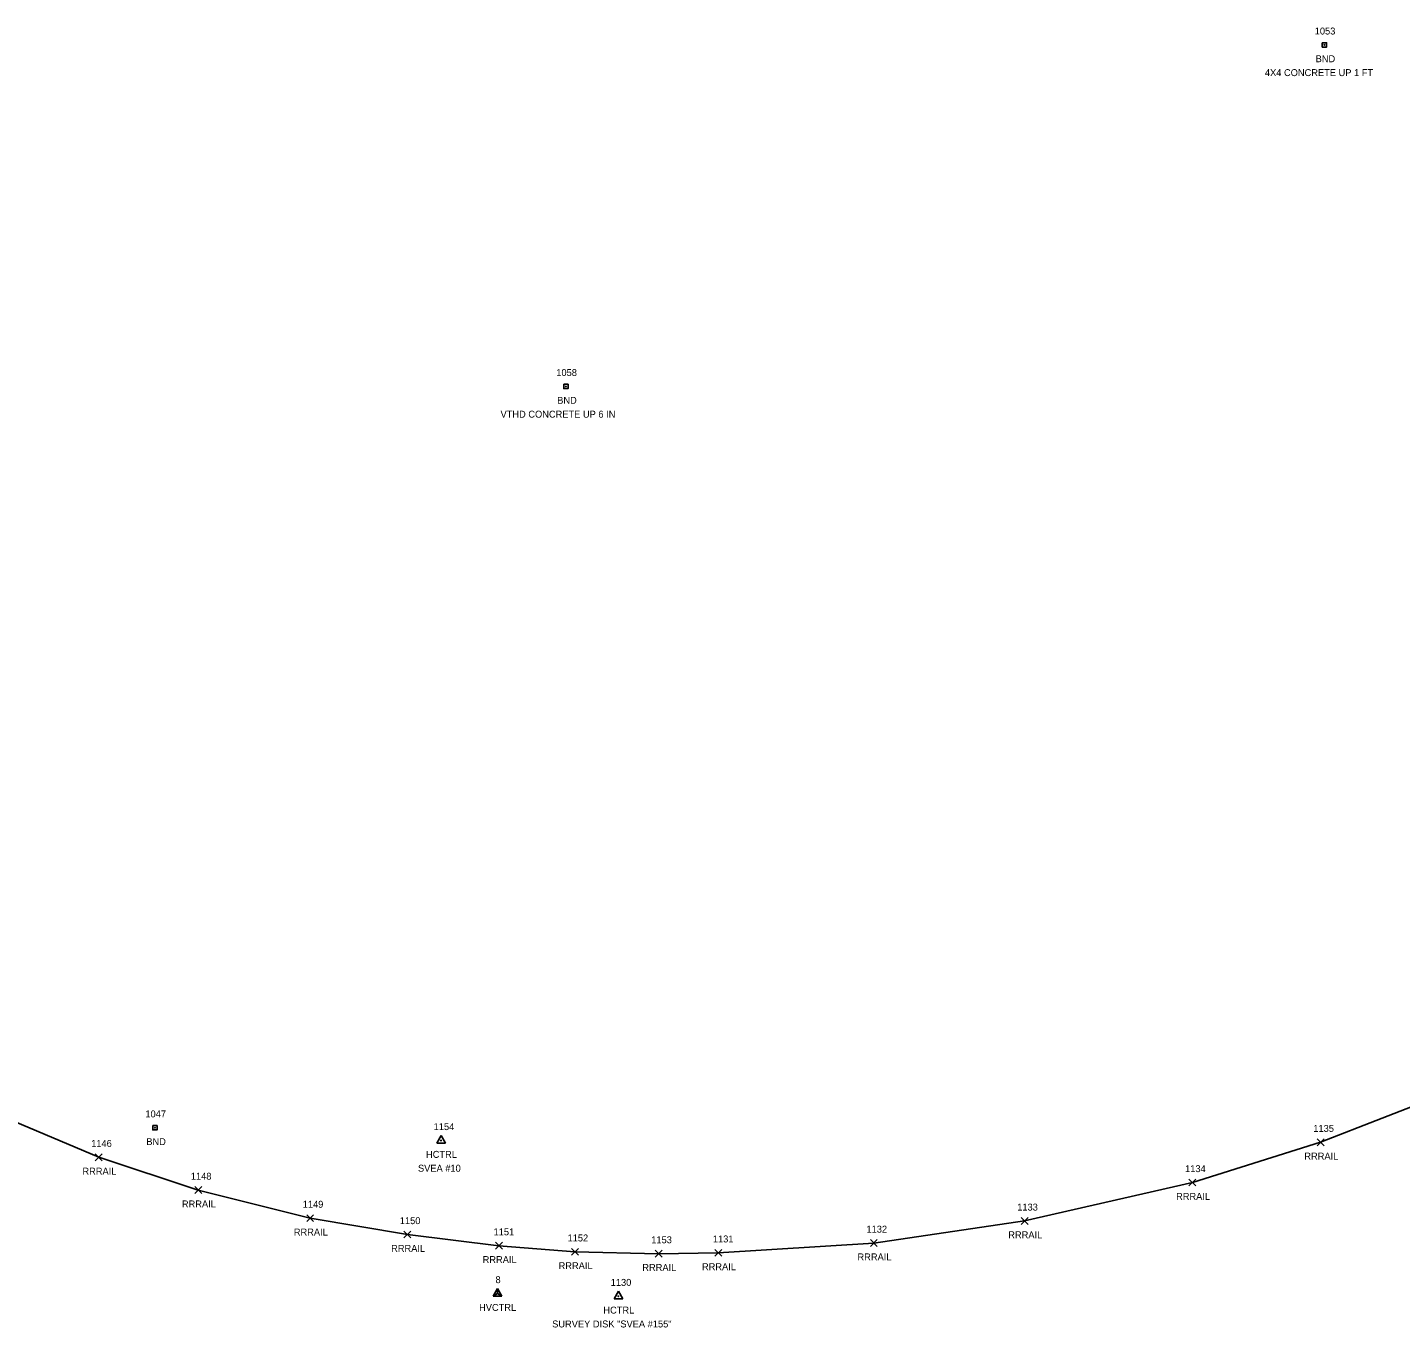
# Model space of a CAD drawing. Extents: x 1764889 to 1767296, y 695936 to 698960.
# Drawn here: x 1765286.6 to 1765682.8, y 695935.6 to 696310.6 of the extents above; entities that cross this region are included whole.
import ezdxf

# ---------------------------------------------------------------- set-up
doc = ezdxf.new("R2010")
doc.units = 0
for name, color, linetype in [('C_A', 7, 'Continuous'), ('C_C', 7, 'Continuous'), ('C_I', 7, 'Continuous'), ('CPH', 7, 'Continuous'), ('CPSM', 7, 'Continuous'), ('Level 18', 7, 'Continuous'), ('M_A', 7, 'Continuous'), ('M_C', 7, 'Continuous'), ('M_I', 7, 'Continuous'), ('R_A', 7, 'Continuous'), ('R_I', 7, 'Continuous'), ('R_TIC', 7, 'Continuous'), ('RR', 7, 'Continuous')]:
    doc.layers.add(name, color=color, linetype=linetype)

msp = doc.modelspace()

# ---------------------------------------------------------------- linework, layer by layer
at = {"layer": 'CPH'}
for p, q in [((1765404.64, 695988.84), (1765405.89, 695991.01)), ((1765404.64, 695988.84), (1765407.14, 695988.84)), ((1765407.14, 695988.84), (1765405.89, 695991.01)), ((1765405.89, 695989.56), (1765405.89, 695989.56)), ((1765455.81, 695943.92), (1765457.06, 695946.09)), ((1765455.81, 695943.92), (1765458.31, 695943.92)), ((1765458.31, 695943.92), (1765457.06, 695946.09)), ((1765457.06, 695944.64), (1765457.06, 695944.64))]:
    msp.add_line(p, q, dxfattribs=at)
for centre in [(1765405.89, 695989.56), (1765457.06, 695944.64)]:
    msp.add_circle(centre, 0.0833, dxfattribs=at)
at = {"layer": 'CPSM'}
for p, q in [((1765420.93, 695944.7), (1765422.18, 695946.86)), ((1765420.93, 695944.7), (1765422.18, 695946.86)), ((1765420.93, 695944.7), (1765422.18, 695946.86)), ((1765420.93, 695944.7), (1765422.18, 695945.42)), ((1765420.93, 695944.7), (1765422.18, 695945.42)), ((1765420.93, 695944.7), (1765422.18, 695945.42)), ((1765420.93, 695944.7), (1765423.43, 695944.7)), ((1765420.93, 695944.7), (1765423.43, 695944.7)), ((1765420.93, 695944.7), (1765423.43, 695944.7)), ((1765423.43, 695944.7), (1765422.18, 695946.86)), ((1765422.18, 695945.42), (1765422.18, 695946.86)), ((1765423.43, 695944.7), (1765422.18, 695946.86)), ((1765422.18, 695945.42), (1765422.18, 695946.86)), ((1765423.43, 695944.7), (1765422.18, 695946.86)), ((1765422.18, 695945.42), (1765422.18, 695946.86)), ((1765422.18, 695945.42), (1765422.18, 695945.42)), ((1765422.18, 695945.42), (1765423.43, 695944.7)), ((1765422.18, 695945.42), (1765422.18, 695945.42)), ((1765422.18, 695945.42), (1765423.43, 695944.7)), ((1765422.18, 695945.42), (1765422.18, 695945.42)), ((1765422.18, 695945.42), (1765423.43, 695944.7))]:
    msp.add_line(p, q, dxfattribs=at)
at = {"layer": 'Level 18'}
for points in [[(1765660.15, 696306.2), (1765661.4, 696306.2), (1765661.4, 696304.95), (1765660.15, 696304.95)], [(1765441.29, 696207.69), (1765442.54, 696207.69), (1765442.54, 696206.43), (1765441.29, 696206.43)], [(1765322.72, 695993.85), (1765323.97, 695993.85), (1765323.97, 695992.6), (1765322.72, 695992.6)]]:
    msp.add_lwpolyline(points, close=True, dxfattribs=at)
for centre in [(1765660.78, 696305.58), (1765441.92, 696207.06), (1765323.35, 695993.23)]:
    msp.add_circle(centre, 0.0833, dxfattribs=at)
at = {"layer": 'R_TIC'}
for points in [[(1765658.71, 695988.05), (1765660.71, 695990.05)], [(1765660.71, 695988.05), (1765658.71, 695990.05)], [(1765306.12, 695983.71), (1765308.12, 695985.71)], [(1765308.12, 695983.71), (1765306.12, 695985.71)], [(1765334.82, 695974.26), (1765336.82, 695976.26)], [(1765336.82, 695974.26), (1765334.82, 695976.26)], [(1765621.7, 695976.44), (1765623.7, 695978.44)], [(1765623.7, 695976.44), (1765621.7, 695978.44)], [(1765367.12, 695966.16), (1765369.12, 695968.16)], [(1765369.12, 695966.16), (1765367.12, 695968.16)], [(1765573.28, 695965.35), (1765575.28, 695967.35)], [(1765575.28, 695965.35), (1765573.28, 695967.35)], [(1765395.2, 695961.44), (1765397.2, 695963.44)], [(1765397.2, 695961.44), (1765395.2, 695963.44)], [(1765421.61, 695958.21), (1765423.61, 695960.21)], [(1765423.61, 695958.21), (1765421.61, 695960.21)], [(1765529.77, 695958.99), (1765531.77, 695960.99)], [(1765531.77, 695958.99), (1765529.77, 695960.99)], [(1765443.52, 695956.45), (1765445.52, 695958.45)], [(1765445.52, 695956.45), (1765443.52, 695958.45)], [(1765467.68, 695955.92), (1765469.68, 695957.92)], [(1765469.68, 695955.92), (1765467.68, 695957.92)], [(1765467.68, 695955.92), (1765469.68, 695957.92)], [(1765469.68, 695955.92), (1765467.68, 695957.92)], [(1765484.89, 695956.16), (1765486.89, 695958.16)], [(1765486.89, 695956.16), (1765484.89, 695958.16)], [(1765484.89, 695956.16), (1765486.89, 695958.16)], [(1765486.89, 695956.16), (1765484.89, 695958.16)]]:
    msp.add_lwpolyline(points, dxfattribs=at)
at = {"layer": 'RR'}
for points in [[(1765485.89, 695957.16), (1765530.77, 695959.99), (1765574.28, 695966.35), (1765622.7, 695977.44), (1765659.71, 695989.05), (1765695.23, 696002.92), (1765717.69, 696013.3), (1765746.18, 696027.96), (1765770.97, 696042.3), (1765798.88, 696060.7), (1765825.33, 696080.52), (1765848.78, 696100.46)], [(1765204.41, 696036.98), (1765236.61, 696018.12), (1765273.6, 695998.88), (1765307.12, 695984.71), (1765335.82, 695975.26), (1765368.12, 695967.16), (1765396.2, 695962.44), (1765422.61, 695959.21), (1765444.52, 695957.45), (1765468.68, 695956.92)], [(1765485.89, 695957.16), (1765468.68, 695956.92)]]:
    msp.add_lwpolyline(points, dxfattribs=at)

# ---------------------------------------------------------------- texts
at = {"layer": 'C_A'}
for s, p in [('HCTRL', (1765401.56, 695984.56)), ('HVCTRL', (1765416.87, 695940.42)), ('HVCTRL', (1765416.87, 695940.42)), ('HVCTRL', (1765416.87, 695940.42)), ('HCTRL', (1765452.73, 695939.64))]:
    msp.add_text(s, height=2, dxfattribs=at).set_placement(p)
at = {"layer": 'C_C'}
for s, p in [('SVEA #10', (1765399.24, 695980.56)), ('SURVEY DISK "SVEA #155"', (1765437.96, 695935.64))]:
    msp.add_text(s, height=2, dxfattribs=at).set_placement(p)
at = {"layer": 'C_I'}
for s, p in [('1154', (1765403.76, 695992.56)), ('8', (1765421.61, 695948.42)), ('8', (1765421.61, 695948.42)), ('8', (1765421.61, 695948.42)), ('1130', (1765454.85, 695947.64))]:
    msp.add_text(s, height=2, dxfattribs=at).set_placement(p)
at = {"layer": 'M_A'}
for p in [(1765658.26, 696300.58), (1765439.41, 696202.06), (1765320.84, 695988.23)]:
    msp.add_text('BND', height=2, dxfattribs=at).set_placement(p)
at = {"layer": 'M_C'}
for s, p in [('4X4 CONCRETE UP 1 FT', (1765643.63, 696296.58)), ('VTHD CONCRETE UP 6 IN', (1765423.06, 696198.06))]:
    msp.add_text(s, height=2, dxfattribs=at).set_placement(p)
at = {"layer": 'M_I'}
for s, p in [('1053', (1765658, 696308.58)), ('1058', (1765439.15, 696210.06)), ('1047', (1765320.58, 695996.23))]:
    msp.add_text(s, height=2, dxfattribs=at).set_placement(p)
at = {"layer": 'R_A'}
for p in [(1765655, 695984.05), (1765302.41, 695979.71), (1765331.11, 695970.26), (1765617.99, 695972.44), (1765363.41, 695962.16), (1765569.57, 695961.35), (1765391.49, 695957.44), (1765417.9, 695954.21), (1765526.06, 695954.99), (1765439.81, 695952.45), (1765463.97, 695951.92), (1765463.97, 695951.92), (1765481.18, 695952.16), (1765481.18, 695952.16)]:
    msp.add_text('RRRAIL', height=2, dxfattribs=at).set_placement(p)
at = {"layer": 'R_I'}
for s, p in [('1135', (1765657.59, 695992.05)), ('1146', (1765304.94, 695987.71)), ('1148', (1765333.69, 695978.26)), ('1134', (1765620.58, 695980.44)), ('1149', (1765365.98, 695970.16)), ('1150', (1765393.99, 695965.44)), ('1133', (1765572.15, 695969.35)), ('1151', (1765421.05, 695962.21)), ('1132', (1765528.65, 695962.99)), ('1152', (1765442.39, 695960.45)), ('1153', (1765466.55, 695959.92)), ('1153', (1765466.55, 695959.92)), ('1131', (1765484.33, 695960.16)), ('1131', (1765484.33, 695960.16))]:
    msp.add_text(s, height=2, dxfattribs=at).set_placement(p)

doc.saveas('drawing.dxf')
